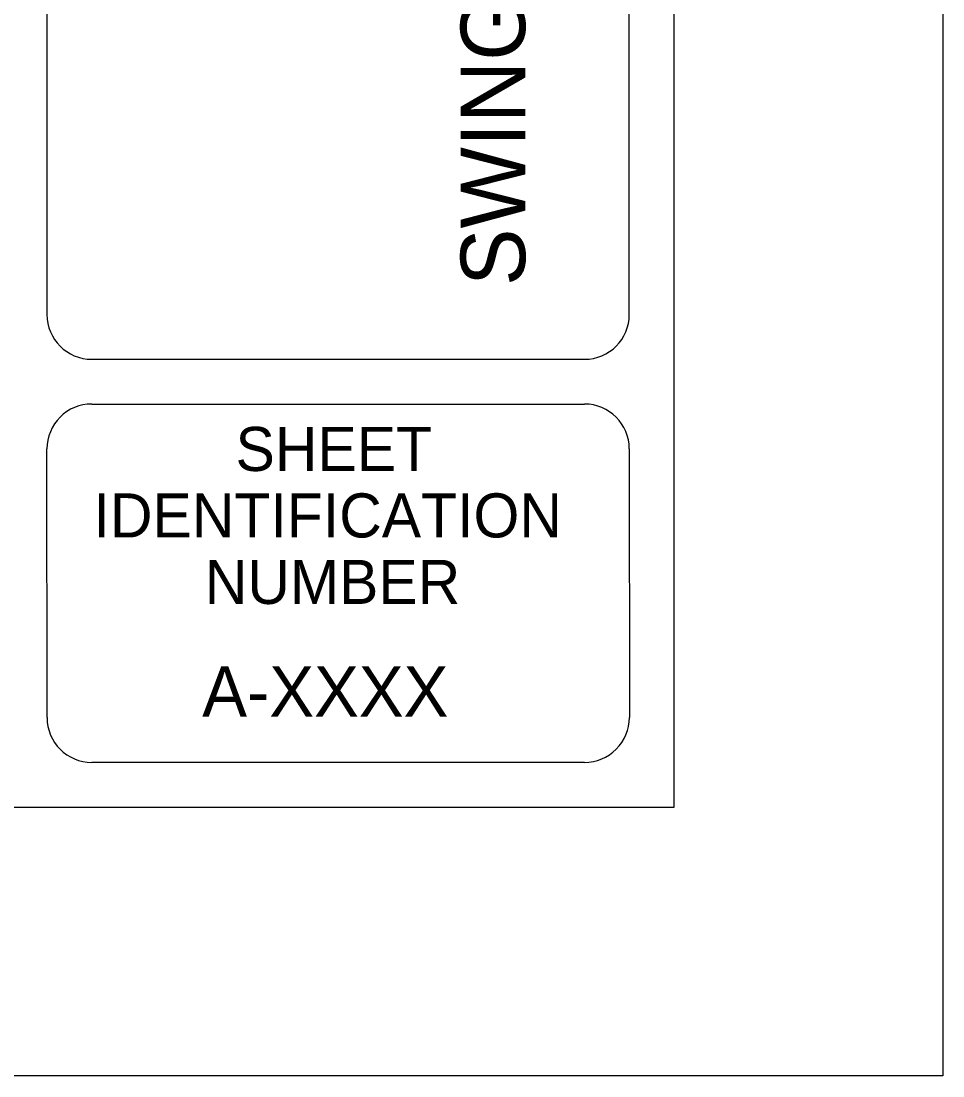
# Model space of a CAD drawing. Extents: x 22371.58 to 22374.41, y 22370.57 to 22372.4.
# Drawn here: x 22374.1973 to 22374.4116, y 22370.5694 to 22370.8148 of the extents above; entities that cross this region are included whole.
import ezdxf

# ---------------------------------------------------------------- set-up
doc = ezdxf.new("R2010")
doc.units = 0
for name, color, linetype in [('G-ANNO-SYMB', 7, 'Continuous'), ('G-ANNO-TEXT', 7, 'Continuous'), ('G-ANNO-TTBL', 7, 'Continuous'), ('G-ANNO-TTLB', 7, 'Continuous')]:
    doc.layers.add(name, color=color, linetype=linetype)

msp = doc.modelspace()

# ---------------------------------------------------------------- linework, layer by layer
at = {"layer": 'G-ANNO-SYMB'}
msp.add_lwpolyline([(22371.578305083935, 22372.402778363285), (22374.411638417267, 22372.402778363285), (22374.411638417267, 22370.569445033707), (22371.578305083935, 22370.569445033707)], close=True, dxfattribs=at)
at = {"layer": 'G-ANNO-TTBL'}
msp.add_lwpolyline([(22374.192888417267, 22370.631945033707), (22374.349138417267, 22370.631945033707), (22374.349138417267, 22372.340278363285), (22374.192888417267, 22372.340278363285)], close=True, dxfattribs=at)
for points in [[(22374.203305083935, 22371.042361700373), (22374.203305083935, 22370.74652836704)], [(22374.3387217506, 22370.74652836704), (22374.3387217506, 22371.042361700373)], [(22374.2137217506, 22370.736111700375), (22374.328305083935, 22370.736111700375)], [(22374.21371315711, 22370.725695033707), (22374.328296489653, 22370.725695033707)], [(22374.203313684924, 22370.65277550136), (22374.203296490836, 22370.71527550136)], [(22374.33871315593, 22370.715281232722), (22374.338730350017, 22370.652781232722)], [(22374.32831368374, 22370.642361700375), (22374.2137303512, 22370.642361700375)]]:
    msp.add_lwpolyline(points, dxfattribs=at)
for centre, radius, start, end in [((22374.2137217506, 22370.74652836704), 0.010416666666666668, 180, 270), ((22374.328305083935, 22370.74652836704), 0.01041666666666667, 270, 0), ((22374.21371315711, 22370.71527836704), 0.01041666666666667, 90, 180.0157623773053), ((22374.328296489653, 22370.71527836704), 0.01041666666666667, 0.015762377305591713, 90), ((22374.2137303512, 22370.65277836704), 0.01041666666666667, 180.01576237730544, 270), ((22374.32831368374, 22370.65277836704), 0.01041666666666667, 270, 0.015762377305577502)]:
    msp.add_arc(centre, radius, start, end, dxfattribs=at)

# ---------------------------------------------------------------- texts
at = {"layer": 'G-ANNO-TEXT'}
msp.add_text('SWING GATE SEAL DETAILS', height=0.014999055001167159, rotation=89.99999999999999, dxfattribs=at).set_placement((22374.314503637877, 22370.753142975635))
for s, p in [('SHEET', (22374.247153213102, 22370.710128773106)), ('IDENTIFICATION', (22374.21413102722, 22370.694667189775)), ('NUMBER', (22374.239994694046, 22370.679205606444))]:
    msp.add_text(s, height=0.010253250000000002, dxfattribs=at).set_placement(p)
at = {"layer": 'G-ANNO-TTLB'}
msp.add_text('A-XXXX', height=0.01166666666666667, dxfattribs=at).set_placement((22374.239412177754, 22370.65301942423))

doc.saveas('drawing.dxf')
